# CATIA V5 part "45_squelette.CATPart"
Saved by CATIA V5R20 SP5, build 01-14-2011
Part number: 45_squelette
Publications: "Plan yz", "Droite.1", "Plan.7", "Point.6", "Point.7"
Bounding box of the stored display mesh (mm): x 0 to 0, y 140.362 to 146.362, z -202 to -41
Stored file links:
  C:\Documents and Settings\anizard\Bureau\13\45_squelette.CATPart
  C:\Documents and Settings\anizard\Bureau\13\anizard.CATProduct
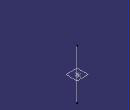
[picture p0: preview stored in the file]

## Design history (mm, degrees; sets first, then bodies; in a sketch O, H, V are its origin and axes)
Set1
  Point1: linked copy from another document
  Plane1: linked copy from another document
  Plane2: linked copy from another document
Body1 (main body)
  Line1: type PtDir, RefPoint Point1, Direction Plane1, Start -107, End 54
  Plane3: type Offset, RefPlane Plane2, Offset 4, reversed
  Point2: type OnPlane, Support Plane3, RefPoint Point1, H 0, V 0, Direction (1, 0, 0)
  Point3: (0, 6, 0), relative to Point2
